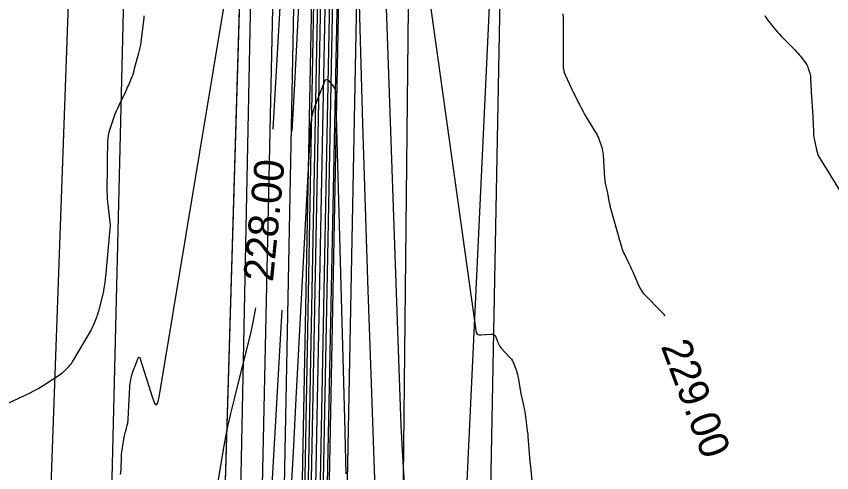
# Model space of a CAD drawing. Extents: x -534410 to -534262, y -1190162 to -1189584.
# Drawn here: x -534375.88 to -534348.62, y -1189726.14 to -1189710.86 of the extents above; entities that cross this region are included whole.
import ezdxf

# ---------------------------------------------------------------- set-up
doc = ezdxf.new("R2010")
doc.units = 0
for name, color, linetype in [('30', 7, 'Continuous'), ('31', 7, 'Continuous'), ('40', 7, 'Continuous'), ('_linie', 7, 'Continuous'), ('_N_osa', 7, 'Continuous'), ('_N_tenká', 7, 'Continuous'), ('_N_tenká_velmi', 7, 'Continuous'), ('_tenka', 7, 'Continuous'), ('Default', 7, 'Continuous'), ('Hranice parcel', 7, 'Continuous')]:
    doc.layers.add(name, color=color, linetype=linetype)

msp = doc.modelspace()

# ---------------------------------------------------------------- linework, layer by layer
at = {"layer": '30'}
for points in [[(-534366.911, -1189707.822), (-534367.302, -1189714.644)], [(-534362.885, -1189726.642), (-534362.961, -1189725.602), (-534363.011, -1189724.559), (-534363.467, -1189711.528), (-534363.552, -1189709.008)], [(-534354.184, -1189720.889), (-534354.22, -1189720.847), (-534354.283, -1189720.779), (-534354.348, -1189720.712), (-534354.818, -1189720.233), (-534354.892, -1189720.151), (-534354.957, -1189720.064), (-534355.013, -1189719.971), (-534355.061, -1189719.872), (-534355.263, -1189719.406), (-534355.295, -1189719.334), (-534355.327, -1189719.263), (-534355.36, -1189719.193), (-534355.394, -1189719.122), (-534355.545, -1189718.817), (-534355.572, -1189718.759), (-534355.596, -1189718.7), (-534355.617, -1189718.641), (-534355.637, -1189718.58), (-534355.708, -1189718.336), (-534355.725, -1189718.275), (-534355.743, -1189718.214), (-534355.76, -1189718.152), (-534355.777, -1189718.091), (-534356.019, -1189717.212), (-534356.028, -1189717.176), (-534356.037, -1189717.14), (-534356.045, -1189717.103), (-534356.052, -1189717.066), (-534356.077, -1189716.918), (-534356.084, -1189716.881), (-534356.091, -1189716.845), (-534356.098, -1189716.808), (-534356.106, -1189716.771), (-534356.166, -1189716.508), (-534356.178, -1189716.452), (-534356.187, -1189716.395), (-534356.194, -1189716.338), (-534356.199, -1189716.281), (-534356.248, -1189715.494), (-534356.255, -1189715.427), (-534356.266, -1189715.36), (-534356.282, -1189715.294), (-534356.302, -1189715.23), (-534356.392, -1189714.973), (-534356.416, -1189714.909), (-534356.443, -1189714.848), (-534356.474, -1189714.787), (-534356.508, -1189714.729), (-534356.822, -1189714.218), (-534356.877, -1189714.126), (-534356.93, -1189714.033), (-534356.981, -1189713.939), (-534357.03, -1189713.844), (-534357.246, -1189713.413), (-534357.282, -1189713.341), (-534357.317, -1189713.269), (-534357.351, -1189713.196), (-534357.384, -1189713.123), (-534357.517, -1189712.83), (-534357.545, -1189712.756), (-534357.566, -1189712.68), (-534357.578, -1189712.603), (-534357.583, -1189712.523), (-534357.583, -1189711.08), (-534357.583, -1189711.042), (-534357.584, -1189711.005), (-534357.586, -1189710.968), (-534357.588, -1189710.93), (-534357.599, -1189710.781)], [(-534371.611, -1189710.844), (-534371.614, -1189710.875), (-534371.618, -1189710.937), (-534371.619, -1189710.952), (-534371.62, -1189710.968), (-534371.622, -1189710.983), (-534371.624, -1189710.998), (-534371.718, -1189711.722), (-534371.732, -1189711.816), (-534371.749, -1189711.91), (-534371.769, -1189712.003), (-534371.792, -1189712.095), (-534371.934, -1189712.623), (-534371.954, -1189712.697), (-534371.98, -1189712.795), (-534371.987, -1189712.82), (-534371.995, -1189712.844), (-534372.004, -1189712.868), (-534372.013, -1189712.891), (-534372.133, -1189713.172), (-534372.157, -1189713.226), (-534372.181, -1189713.28), (-534372.206, -1189713.334), (-534372.232, -1189713.388), (-534372.457, -1189713.849), (-534372.501, -1189713.944), (-534372.543, -1189714.041), (-534372.582, -1189714.139), (-534372.618, -1189714.238), (-534372.758, -1189714.643), (-534372.788, -1189714.744), (-534372.81, -1189714.847), (-534372.824, -1189714.952), (-534372.83, -1189715.058), (-534372.839, -1189715.699), (-534372.84, -1189715.723), (-534372.84, -1189715.748), (-534372.84, -1189715.772), (-534372.84, -1189715.796), (-534372.84, -1189715.893), (-534372.84, -1189715.917), (-534372.84, -1189715.941), (-534372.84, -1189715.966), (-534372.841, -1189715.99), (-534372.85, -1189716.619), (-534372.85, -1189716.732), (-534372.846, -1189716.844), (-534372.839, -1189716.957), (-534372.829, -1189717.069), (-534372.747, -1189717.839), (-534372.747, -1189717.849), (-534372.747, -1189717.85), (-534372.9, -1189719.581), (-534372.905, -1189719.63), (-534372.91, -1189719.679), (-534372.916, -1189719.727), (-534372.923, -1189719.776), (-534372.952, -1189719.97), (-534372.959, -1189720.019), (-534372.968, -1189720.067), (-534372.979, -1189720.115), (-534372.99, -1189720.162), (-534373.136, -1189720.736), (-534373.151, -1189720.79), (-534373.167, -1189720.844), (-534373.185, -1189720.897), (-534373.204, -1189720.949), (-534373.285, -1189721.158), (-534373.306, -1189721.21), (-534373.329, -1189721.261), (-534373.354, -1189721.311), (-534373.382, -1189721.359), (-534374.008, -1189722.424), (-534374.038, -1189722.472), (-534374.072, -1189722.517), (-534374.107, -1189722.561), (-534374.146, -1189722.602), (-534374.307, -1189722.764), (-534374.348, -1189722.803), (-534374.391, -1189722.84), (-534374.435, -1189722.874), (-534374.482, -1189722.906), (-534375.005, -1189723.243), (-534375.109, -1189723.308), (-534375.215, -1189723.369), (-534375.323, -1189723.427), (-534375.433, -1189723.48), (-534377.082, -1189724.25)], [(-534366.691, -1189726.823), (-534366.604, -1189725.242), (-534366.519, -1189723.661), (-534366.03, -1189714.51), (-534366.014, -1189714.344), (-534365.985, -1189714.18), (-534365.944, -1189714.02), (-534365.889, -1189713.862), (-534365.562, -1189713.034), (-534365.539, -1189712.992), (-534365.511, -1189712.975), (-534365.479, -1189712.982), (-534365.443, -1189713.014), (-534365.291, -1189713.19), (-534365.258, -1189713.235), (-534365.233, -1189713.285), (-534365.218, -1189713.337), (-534365.212, -1189713.394), (-534364.91, -1189724.332), (-534364.858, -1189726.175)], [(-534367.885, -1189720.616), (-534367.961, -1189721.046), (-534368.052, -1189721.483), (-534368.156, -1189721.917), (-534368.612, -1189723.709), (-534368.72, -1189724.153), (-534368.819, -1189724.599), (-534368.908, -1189725.047), (-534368.987, -1189725.497), (-534370.447, -1189734.343)]]:
    msp.add_lwpolyline(points, dxfattribs=at)
at = {"layer": '31'}
for points in [[(-534364.841, -1189694.956), (-534364.38, -1189711.668), (-534364.3, -1189714.46), (-534364.216, -1189717.252), (-534364.126, -1189720.044), (-534364.031, -1189722.836), (-534363.168, -1189747.541), (-534363.164, -1189747.619), (-534363.158, -1189747.696), (-534363.15, -1189747.773)], [(-534366.657, -1189714.707), (-534366.581, -1189713.329), (-534366.452, -1189710.949), (-534365.716, -1189697.176)], [(-534372.392, -1189726.202), (-534372.383, -1189726.121), (-534372.378, -1189726.039), (-534372.362, -1189725.613), (-534372.358, -1189725.536), (-534372.351, -1189725.458), (-534372.342, -1189725.381), (-534372.33, -1189725.304), (-534372.268, -1189724.946), (-534372.259, -1189724.895), (-534372.248, -1189724.845), (-534372.237, -1189724.795), (-534372.223, -1189724.745), (-534372.168, -1189724.547), (-534372.156, -1189724.497), (-534372.146, -1189724.446), (-534372.139, -1189724.396), (-534372.135, -1189724.344), (-534372.082, -1189723.265), (-534372.079, -1189723.222), (-534372.075, -1189723.18), (-534372.069, -1189723.138), (-534372.062, -1189723.096), (-534372.023, -1189722.896), (-534372.018, -1189722.871), (-534372.011, -1189722.845), (-534372.004, -1189722.82), (-534371.995, -1189722.795), (-534371.96, -1189722.695), (-534371.951, -1189722.671), (-534371.941, -1189722.646), (-534371.932, -1189722.621), (-534371.922, -1189722.597), (-534371.812, -1189722.325), (-534371.791, -1189722.285), (-534371.771, -1189722.273), (-534371.752, -1189722.287), (-534371.734, -1189722.328), (-534371.327, -1189723.633), (-534371.258, -1189723.809), (-534371.197, -1189723.865), (-534371.144, -1189723.801), (-534371.1, -1189723.617), (-534368.388, -1189707.194)], [(-534362.375, -1189708.044), (-534360.52, -1189721.385), (-534360.501, -1189721.451), (-534360.466, -1189721.497), (-534360.414, -1189721.522), (-534360.345, -1189721.527), (-534359.986, -1189721.502), (-534359.939, -1189721.505), (-534359.9, -1189721.521), (-534359.87, -1189721.55), (-534359.848, -1189721.592), (-534359.778, -1189721.784), (-534359.759, -1189721.831), (-534359.735, -1189721.875), (-534359.707, -1189721.917), (-534359.674, -1189721.956), (-534359.366, -1189722.295), (-534359.327, -1189722.341), (-534359.294, -1189722.391), (-534359.266, -1189722.444), (-534359.242, -1189722.5), (-534359.16, -1189722.73), (-534359.141, -1189722.787), (-534359.124, -1189722.846), (-534359.11, -1189722.905), (-534359.099, -1189722.965), (-534359.012, -1189723.491), (-534359.003, -1189723.542), (-534358.993, -1189723.592), (-534358.981, -1189723.643), (-534358.969, -1189723.693), (-534358.917, -1189723.892), (-534358.905, -1189723.942), (-534358.894, -1189723.993), (-534358.885, -1189724.043), (-534358.877, -1189724.094), (-534358.806, -1189724.631), (-534358.793, -1189724.738), (-534358.781, -1189724.845), (-534358.771, -1189724.952), (-534358.763, -1189725.059), (-534358.71, -1189725.787), (-534358.709, -1189725.798), (-534358.708, -1189725.81), (-534358.706, -1189725.821), (-534358.703, -1189725.832), (-534358.693, -1189725.877), (-534358.691, -1189725.888), (-534358.689, -1189725.9), (-534358.687, -1189725.911), (-534358.686, -1189725.922), (-534358.615, -1189726.656)], [(-534350.852, -1189710.838), (-534350.807, -1189710.909), (-534350.757, -1189710.977), (-534350.49, -1189711.311), (-534350.427, -1189711.388), (-534350.362, -1189711.464), (-534350.295, -1189711.537), (-534350.225, -1189711.608), (-534349.838, -1189711.999), (-534349.791, -1189712.047), (-534349.747, -1189712.097), (-534349.704, -1189712.148), (-534349.663, -1189712.201), (-534349.473, -1189712.456), (-534349.449, -1189712.491), (-534349.429, -1189712.527), (-534349.411, -1189712.565), (-534349.397, -1189712.604), (-534349.347, -1189712.764), (-534349.336, -1189712.805), (-534349.328, -1189712.845), (-534349.322, -1189712.887), (-534349.319, -1189712.928), (-534349.311, -1189713.171), (-534349.309, -1189713.225), (-534349.307, -1189713.28), (-534349.304, -1189713.334), (-534349.301, -1189713.389), (-534349.249, -1189714.217), (-534349.245, -1189714.279), (-534349.242, -1189714.342), (-534349.239, -1189714.405), (-534349.237, -1189714.468), (-534349.229, -1189714.719), (-534349.226, -1189714.782), (-534349.22, -1189714.844), (-534349.211, -1189714.906), (-534349.2, -1189714.968), (-534349.125, -1189715.334), (-534349.104, -1189715.414), (-534349.078, -1189715.491), (-534349.044, -1189715.566), (-534349.003, -1189715.638), (-534347.853, -1189717.495)], [(-534367.841, -1189735.505), (-534366.993, -1189720.703)]]:
    msp.add_lwpolyline(points, dxfattribs=at)
at = {"layer": '_linie'}
for points in [[(-534366.12, -1189620.81), (-534364.52, -1189627.2), (-534365.69, -1189653.8), (-534366.76, -1189684.81), (-534368.14, -1189748.73), (-534368.38, -1189779.14), (-534368.65, -1189820.64), (-534368.59, -1189847.58), (-534367.2, -1189913.8)], [(-534363.12, -1189621.02), (-534362.79, -1189621.58), (-534361.82, -1189627.79), (-534363.46, -1189653.55), (-534365.47, -1189684.77), (-534366.65, -1189748.83), (-534366.75, -1189779.47), (-534366.9, -1189820.47), (-534366.95, -1189846.72), (-534366.338, -1189888.804), (-534363.85, -1189911.95), (-534357.07, -1189929.19), (-534352.334, -1189940.856)], [(-534359.03, -1189621.26), (-534359.41, -1189621.83), (-534360.84, -1189627.76), (-534362.92, -1189653.56), (-534364.64, -1189685), (-534365.94, -1189748.9), (-534366.02, -1189779.52), (-534366.03, -1189820.5), (-534366.48, -1189846.73), (-534365.511, -1189888.873), (-534362.72, -1189912.12), (-534356.62, -1189928.64), (-534351.589, -1189940.594)]]:
    msp.add_lwpolyline(points, dxfattribs=at)
at = {"layer": '_N_osa'}
msp.add_lwpolyline([(-534351.95, -1189940.722), (-534356.845, -1189928.915), (-534363.285, -1189912.035), (-534365.925, -1189888.838), (-534366.715, -1189846.725), (-534366.465, -1189820.485), (-534366.385, -1189779.495), (-534366.295, -1189748.865), (-534365.055, -1189684.885), (-534363.19, -1189653.555), (-534361.333, -1189627.822)], dxfattribs=at)
at = {"layer": '_N_tenká'}
for points in [[(-534352.92, -1189941.124), (-534357.821, -1189929.303), (-534364.313, -1189912.285), (-534366.973, -1189888.908), (-534367.765, -1189846.73), (-534367.515, -1189820.479), (-534367.435, -1189779.492), (-534367.345, -1189748.853), (-534366.104, -1189684.844), (-534364.238, -1189653.486), (-534362.424, -1189628.352), (-534361.782, -1189627.792)], [(-534352.089, -1189940.779), (-534356.984, -1189928.97), (-534363.432, -1189912.071), (-534366.074, -1189888.848), (-534366.865, -1189846.726), (-534366.615, -1189820.484), (-534366.535, -1189779.495), (-534366.445, -1189748.863), (-534365.205, -1189684.879), (-534363.34, -1189653.545), (-534361.483, -1189627.812)], [(-534351.812, -1189940.664), (-534356.706, -1189928.86), (-534363.138, -1189911.999), (-534365.775, -1189888.828), (-534366.565, -1189846.724), (-534366.315, -1189820.486), (-534366.235, -1189779.495), (-534366.145, -1189748.867), (-534364.905, -1189684.891), (-534363.04, -1189653.565), (-534361.184, -1189627.831)], [(-534350.98, -1189940.319), (-534355.869, -1189928.527), (-534362.257, -1189911.785), (-534364.876, -1189888.769), (-534365.665, -1189846.72), (-534365.415, -1189820.491), (-534365.335, -1189779.498), (-534365.245, -1189748.877), (-534364.006, -1189684.926), (-534362.142, -1189653.624), (-534360.329, -1189628.488), (-534360.884, -1189627.851)]]:
    msp.add_lwpolyline(points, dxfattribs=at)
at = {"layer": '_N_tenká_velmi'}
for points in [[(-534352.366, -1189940.894), (-534357.263, -1189929.081), (-534363.726, -1189912.142), (-534366.374, -1189888.868), (-534367.165, -1189846.727), (-534366.915, -1189820.482), (-534366.835, -1189779.494), (-534366.745, -1189748.86), (-534365.505, -1189684.867), (-534363.639, -1189653.525), (-534361.782, -1189627.792)], [(-534352.181, -1189940.817), (-534357.077, -1189929.007), (-534363.53, -1189912.095), (-534366.174, -1189888.855), (-534366.965, -1189846.726), (-534366.715, -1189820.484), (-534366.635, -1189779.494), (-534366.545, -1189748.862), (-534365.305, -1189684.875), (-534363.439, -1189653.539), (-534361.583, -1189627.805)], [(-534351.719, -1189940.626), (-534356.613, -1189928.823), (-534363.04, -1189911.975), (-534365.675, -1189888.822), (-534366.465, -1189846.724), (-534366.215, -1189820.486), (-534366.135, -1189779.496), (-534366.045, -1189748.868), (-534364.805, -1189684.895), (-534362.941, -1189653.571), (-534361.084, -1189627.838)], [(-534351.534, -1189940.549), (-534356.427, -1189928.749), (-534362.844, -1189911.928), (-534365.475, -1189888.808), (-534366.265, -1189846.723), (-534366.015, -1189820.488), (-534365.935, -1189779.496), (-534365.845, -1189748.87), (-534364.605, -1189684.903), (-534362.741, -1189653.585), (-534360.884, -1189627.851)]]:
    msp.add_lwpolyline(points, dxfattribs=at)
at = {"layer": '_tenka'}
for points in [[(-534349.13, -1189939.73), (-534354.63, -1189926.96), (-534362.03, -1189907.65), (-534364.521, -1189888.74), (-534364.47, -1189846.64), (-534364.29, -1189820.63), (-534364.22, -1189780.69), (-534363.18, -1189749.38), (-534362.5, -1189685.39), (-534360.27, -1189651.6), (-534357.03, -1189627.34), (-534354.77, -1189620.37)], [(-534366.12, -1189620.81), (-534364.52, -1189627.2), (-534365.69, -1189653.8), (-534366.76, -1189684.81), (-534368.14, -1189748.73), (-534368.38, -1189779.14), (-534368.65, -1189820.64), (-534368.59, -1189847.58), (-534367.2, -1189913.8)], [(-534366.12, -1189620.81), (-534364.52, -1189627.2), (-534365.69, -1189653.8), (-534366.76, -1189684.81), (-534368.14, -1189748.73), (-534368.38, -1189779.14), (-534368.65, -1189820.64), (-534368.59, -1189847.58), (-534367.2, -1189913.8)], [(-534363.12, -1189621.02), (-534362.79, -1189621.58), (-534361.82, -1189627.79), (-534363.46, -1189653.55), (-534365.47, -1189684.77), (-534366.65, -1189748.83), (-534366.75, -1189779.47), (-534366.9, -1189820.47), (-534366.95, -1189846.72), (-534366.338, -1189888.804), (-534363.85, -1189911.95), (-534357.07, -1189929.19), (-534352.334, -1189940.856)], [(-534363.12, -1189621.02), (-534362.79, -1189621.58), (-534361.82, -1189627.79), (-534363.46, -1189653.55), (-534365.47, -1189684.77), (-534366.65, -1189748.83), (-534366.75, -1189779.47), (-534366.9, -1189820.47), (-534366.95, -1189846.72), (-534366.338, -1189888.804), (-534363.85, -1189911.95), (-534357.07, -1189929.19), (-534352.334, -1189940.856)], [(-534359.03, -1189621.26), (-534359.41, -1189621.83), (-534360.84, -1189627.76), (-534362.92, -1189653.56), (-534364.64, -1189685), (-534365.94, -1189748.9), (-534366.02, -1189779.52), (-534366.03, -1189820.5), (-534366.48, -1189846.73), (-534365.511, -1189888.873), (-534362.72, -1189912.12), (-534356.62, -1189928.64), (-534351.589, -1189940.594)], [(-534359.03, -1189621.26), (-534359.41, -1189621.83), (-534360.84, -1189627.76), (-534362.92, -1189653.56), (-534364.64, -1189685), (-534365.94, -1189748.9), (-534366.02, -1189779.52), (-534366.03, -1189820.5), (-534366.48, -1189846.73), (-534365.511, -1189888.873), (-534362.72, -1189912.12), (-534356.62, -1189928.64), (-534351.589, -1189940.594)], [(-534368.65, -1189626.81), (-534368.65, -1189626.81), (-534367.31, -1189654.04), (-534367.67, -1189685.23), (-534369.56, -1189748.93), (-534369.48, -1189778.6), (-534369.45, -1189820.62), (-534369.45, -1189847.87), (-534371.206, -1189896.071), (-534372.39, -1189914.47)]]:
    msp.add_lwpolyline(points, dxfattribs=at)
at = {"layer": 'Default'}
msp.add_line((-534367.67, -1189685.23), (-534369.56, -1189748.93), dxfattribs=at)
msp.add_lwpolyline([(-534349.13, -1189939.73), (-534354.63, -1189926.96), (-534362.03, -1189907.65), (-534364.521, -1189888.74), (-534364.47, -1189846.64), (-534364.29, -1189820.63), (-534364.22, -1189780.69), (-534363.18, -1189749.38), (-534362.5, -1189685.39), (-534360.27, -1189651.6), (-534357.03, -1189627.34), (-534354.77, -1189620.37)], dxfattribs=at)
at = {"layer": 'Hranice parcel'}
for p, q in [((-534371.04, -1189658.4), (-534373.49, -1189759.21)), ((-534369.14, -1189764.19), (-534367.77, -1189697.34))]:
    msp.add_line(p, q, dxfattribs=at)
for points in [[(-534373.49, -1189759.21), (-534375.27, -1189742.09), (-534373.87, -1189702.99), (-534373.87, -1189662.03), (-534374.42, -1189646.7)], [(-534359.48, -1189697.97), (-534362.6, -1189764.35), (-534362.34, -1189901.56)], [(-534359.48, -1189697.97), (-534360.42, -1189747.8), (-534359.17, -1189788.69), (-534356.86, -1189843.2), (-534358.53, -1189915.98)]]:
    msp.add_lwpolyline(points, dxfattribs=at)

# ---------------------------------------------------------------- texts
at = {"layer": '40'}
for s, rotation, p in [('228.00', 84.4269, (-534367.3, -1189719.771)), ('229.00', 290.4514, (-534354.336, -1189721.904))]:
    msp.add_text(s, height=1, rotation=rotation, dxfattribs=at).set_placement(p)

doc.saveas('drawing.dxf')
